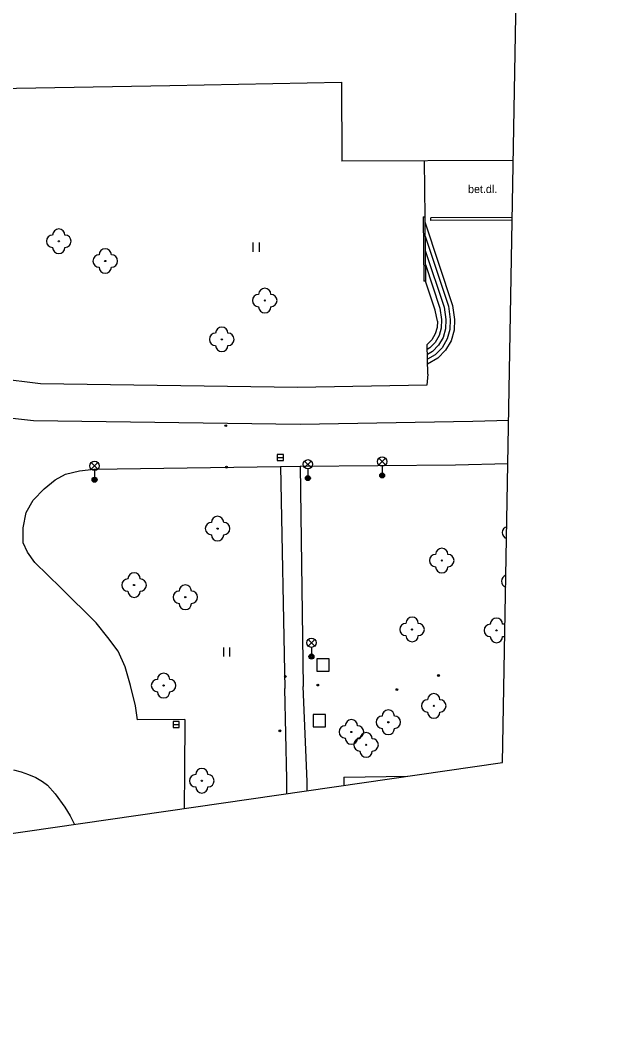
# Model space of a CAD drawing. Extents: x -641829 to -641525, y -1114855 to -1114359.
# Drawn here: x -641572.8 to -641525.3, y -1114854.7 to -1114772 of the extents above; entities that cross this region are included whole.
import ezdxf

# ---------------------------------------------------------------- set-up
doc = ezdxf.new("R2010")
doc.units = 0
for name, color, linetype in [('Vrstva 1', 7, 'Continuous'), ('Vrstva 10', 7, 'Continuous'), ('Vrstva 11', 7, 'Continuous'), ('Vrstva 20', 7, 'Continuous'), ('Vrstva 22', 7, 'Continuous'), ('Vrstva 26', 7, 'Continuous'), ('Vrstva 27', 7, 'Continuous'), ('Vrstva 33', 7, 'Continuous'), ('Vrstva 36', 7, 'Continuous'), ('Vrstva 40', 7, 'Continuous'), ('Vrstva 5', 7, 'Continuous'), ('Vrstva 7', 7, 'Continuous')]:
    doc.layers.add(name, color=color, linetype=linetype)

msp = doc.modelspace()

# ---------------------------------------------------------------- linework, layer by layer
at = {"layer": 'Vrstva 1'}
for p, q in [((-641533.66, -1114832.21), (-641525.3, -1114362.64)), ((-641689.21, -1114854.71), (-641533.66, -1114832.21))]:
    msp.add_line(p, q, dxfattribs=at)
at = {"layer": 'Vrstva 10'}
for p, q in [((-641575.38, -1114804.04), (-641571.75, -1114804.44)), ((-641571.75, -1114804.44), (-641550.1, -1114804.74)), ((-641550.1, -1114804.74), (-641536.08, -1114804.49)), ((-641536.08, -1114804.49), (-641533.165, -1114804.408)), ((-641550.1, -1114808.16), (-641537.48, -1114808.05)), ((-641537.48, -1114808.05), (-641533.228, -1114807.945)), ((-641569.98, -1114809.27), (-641569.14, -1114808.8)), ((-641569.14, -1114808.8), (-641568, -1114808.52)), ((-641568, -1114808.52), (-641566.86, -1114808.4)), ((-641566.86, -1114808.4), (-641551.7, -1114808.17)), ((-641551.7, -1114808.17), (-641550.1, -1114808.16)), ((-641570.89, -1114810), (-641569.98, -1114809.27)), ((-641571.76, -1114810.92), (-641570.89, -1114810)), ((-641572.35, -1114811.92), (-641571.76, -1114810.92)), ((-641572.59, -1114813.15), (-641572.35, -1114811.92)), ((-641572.58, -1114814.38), (-641572.59, -1114813.15)), ((-641572.23, -1114815.14), (-641572.58, -1114814.38)), ((-641571.65, -1114815.97), (-641572.23, -1114815.14)), ((-641569.52, -1114818.04), (-641571.65, -1114815.97)), ((-641566.67, -1114820.87), (-641569.52, -1114818.04)), ((-641565.72, -1114822.05), (-641566.67, -1114820.87)), ((-641564.88, -1114823.17), (-641565.72, -1114822.05)), ((-641564.31, -1114824.45), (-641564.88, -1114823.17)), ((-641563.86, -1114825.96), (-641564.31, -1114824.45)), ((-641563.46, -1114827.61), (-641563.86, -1114825.96)), ((-641563.29, -1114828.75), (-641563.46, -1114827.61)), ((-641559.45, -1114828.72), (-641563.29, -1114828.75)), ((-641559.45, -1114828.72), (-641559.5, -1114832.91)), ((-641573.38, -1114832.81), (-641572.75, -1114832.98)), ((-641572.75, -1114832.98), (-641572.16, -1114833.19)), ((-641572.16, -1114833.19), (-641571.56, -1114833.43)), ((-641571.56, -1114833.43), (-641571.02, -1114833.76)), ((-641559.5, -1114832.91), (-641559.518, -1114835.95)), ((-641571.02, -1114833.76), (-641570.61, -1114834.06)), ((-641570.61, -1114834.06), (-641570, -1114834.74)), ((-641570, -1114834.74), (-641569.19, -1114835.84)), ((-641569.19, -1114835.84), (-641568.77, -1114836.55)), ((-641568.77, -1114836.55), (-641568.418, -1114837.238))]:
    msp.add_line(p, q, dxfattribs=at)
at = {"layer": 'Vrstva 11'}
for p, q in [((-641540.03, -1114783.36), (-641539.98, -1114787.91)), ((-641540.12, -1114787.91), (-641540.06, -1114793.12)), ((-641532.872, -1114787.957), (-641539.5, -1114787.99)), ((-641539.5, -1114788.21), (-641539.5, -1114787.99)), ((-641532.876, -1114788.177), (-641539.5, -1114788.21)), ((-641539.97, -1114788.32), (-641537.72, -1114795.09)), ((-641539.96, -1114789.47), (-641538.06, -1114795.17)), ((-641539.94, -1114790.63), (-641538.41, -1114795.25)), ((-641539.93, -1114791.78), (-641538.75, -1114795.33)), ((-641539.14, -1114795.49), (-641539.91, -1114793.12)), ((-641538.96, -1114796.37), (-641539.14, -1114795.49)), ((-641538.75, -1114795.33), (-641538.63, -1114796.25)), ((-641538.41, -1114795.25), (-641538.28, -1114796.25)), ((-641538.06, -1114795.17), (-641537.92, -1114796.25)), ((-641537.72, -1114795.09), (-641537.57, -1114796.25)), ((-641539.72, -1114800.69), (-641539.79, -1114798.27)), ((-641571.18, -1114801.45), (-641574.98, -1114800.99)), ((-641550.31, -1114801.76), (-641571.18, -1114801.45)), ((-641539.72, -1114800.69), (-641539.81, -1114801.57)), ((-641539.81, -1114801.57), (-641550.31, -1114801.76)), ((-641551.7, -1114808.17), (-641551.33, -1114826.21)), ((-641550.1, -1114808.16), (-641549.84, -1114826.04)), ((-641551.19, -1114833.57), (-641551.33, -1114826.21)), ((-641549.53, -1114833.75), (-641549.84, -1114826.04)), ((-641551.183, -1114834.745), (-641551.19, -1114833.57)), ((-641549.53, -1114834.506), (-641549.53, -1114833.75))]:
    msp.add_line(p, q, dxfattribs=at)
for points in [[(-641538.96, -1114796.37), (-641538.98, -1114796.89), (-641539.13, -1114797.41), (-641539.41, -1114797.89), (-641539.79, -1114798.27)], [(-641538.63, -1114796.25), (-641538.64, -1114796.94), (-641538.81, -1114797.55), (-641539.13, -1114798.1), (-641539.58, -1114798.55), (-641539.78, -1114798.67)], [(-641538.28, -1114796.25), (-641538.29, -1114797), (-641538.49, -1114797.69), (-641538.86, -1114798.32), (-641539.36, -1114798.83), (-641539.77, -1114799.07)], [(-641537.92, -1114796.25), (-641537.94, -1114797.05), (-641538.17, -1114797.82), (-641538.58, -1114798.53), (-641539.15, -1114799.1), (-641539.76, -1114799.47)], [(-641537.57, -1114796.25), (-641537.6, -1114797.1), (-641537.84, -1114797.96), (-641538.3, -1114798.74), (-641538.93, -1114799.38), (-641539.75, -1114799.87)]]:
    msp.add_lwpolyline(points, dxfattribs=at)
at = {"layer": 'Vrstva 20'}
for centre, radius in [((-641556.14, -1114804.86), 0.075), ((-641556.14, -1114804.86), 0.0204), ((-641556.08, -1114808.23), 0.075), ((-641556.08, -1114808.23), 0.0204), ((-641551.3, -1114825.23), 0.075), ((-641551.3, -1114825.23), 0.0204), ((-641538.86, -1114825.15), 0.075), ((-641538.86, -1114825.15), 0.0204), ((-641548.67, -1114825.92), 0.075), ((-641548.67, -1114825.92), 0.0204), ((-641542.24, -1114826.29), 0.075), ((-641542.24, -1114826.29), 0.0204), ((-641551.74, -1114829.64), 0.075), ((-641551.74, -1114829.64), 0.0204)]:
    msp.add_circle(centre, radius, dxfattribs=at)
at = {"layer": 'Vrstva 22'}
for centre in [(-641569.69, -1114789.89), (-641565.92, -1114791.49), (-641552.97, -1114794.7), (-641556.46, -1114797.85), (-641556.8, -1114813.22), (-641538.6, -1114815.81), (-641563.58, -1114817.8), (-641559.42, -1114818.79), (-641541.01, -1114821.41), (-641534.16, -1114821.48), (-641561.18, -1114825.96), (-641539.25, -1114827.61), (-641542.94, -1114828.94), (-641545.94, -1114829.73), (-641544.74, -1114830.78), (-641558.08, -1114833.69)]:
    msp.add_circle(centre, 0.05, dxfattribs=at)
for centre, start, end in [((-641569.69, -1114789.39), 0, 180), ((-641570.19, -1114789.89), 90, 270), ((-641569.19, -1114789.89), 270, 90), ((-641569.69, -1114790.39), 180, 0), ((-641565.92, -1114790.99), 0, 180), ((-641566.42, -1114791.49), 90, 270), ((-641565.42, -1114791.49), 270, 90), ((-641565.92, -1114791.99), 180, 0), ((-641552.97, -1114794.2), 0, 180), ((-641553.47, -1114794.7), 90, 270), ((-641552.47, -1114794.7), 270, 90), ((-641552.97, -1114795.2), 180, 0), ((-641556.46, -1114797.35), 0, 180), ((-641556.96, -1114797.85), 90, 270), ((-641555.96, -1114797.85), 270, 90), ((-641556.46, -1114798.35), 180, 0), ((-641557.3, -1114813.22), 90, 270), ((-641556.8, -1114812.72), 0, 180), ((-641556.3, -1114813.22), 270, 90), ((-641556.8, -1114813.72), 180, 0), ((-641533.19, -1114813.55), 104.97358, 252.98651), ((-641539.1, -1114815.81), 90, 270), ((-641538.6, -1114815.31), 0, 180), ((-641538.1, -1114815.81), 270, 90), ((-641538.6, -1114816.31), 180, 0), ((-641563.58, -1114817.3), 0, 180), ((-641533.26, -1114817.49), 104.99096, 252.96912), ((-641564.08, -1114817.8), 90, 270), ((-641563.08, -1114817.8), 270, 90), ((-641559.42, -1114818.29), 0, 180), ((-641563.58, -1114818.3), 180, 0), ((-641559.92, -1114818.79), 90, 270), ((-641558.92, -1114818.79), 270, 90), ((-641559.42, -1114819.29), 180, 0), ((-641541.01, -1114820.91), 0, 180), ((-641534.16, -1114820.98), 0, 180), ((-641541.51, -1114821.41), 90, 270), ((-641540.51, -1114821.41), 270, 90), ((-641534.66, -1114821.48), 90, 270), ((-641533.66, -1114821.48), 66.52223, 90), ((-641541.01, -1114821.91), 180, 0), ((-641534.16, -1114821.98), 180, 0), ((-641533.66, -1114821.48), 270, 291.43785), ((-641561.18, -1114825.46), 0, 180), ((-641561.68, -1114825.96), 90, 270), ((-641560.68, -1114825.96), 270, 90), ((-641561.18, -1114826.46), 180, 0), ((-641539.75, -1114827.61), 90, 270), ((-641539.25, -1114827.11), 0, 180), ((-641538.75, -1114827.61), 270, 90), ((-641545.94, -1114829.23), 0, 180), ((-641543.44, -1114828.94), 90, 270), ((-641542.94, -1114828.44), 0, 180), ((-641542.44, -1114828.94), 270, 90), ((-641539.25, -1114828.11), 180, 0), ((-641546.44, -1114829.73), 90, 270), ((-641545.44, -1114829.73), 270, 90), ((-641542.94, -1114829.44), 180, 0), ((-641545.94, -1114830.23), 180, 0), ((-641545.24, -1114830.78), 90, 270), ((-641544.74, -1114830.28), 0, 180), ((-641544.24, -1114830.78), 270, 90), ((-641544.74, -1114831.28), 180, 0), ((-641558.08, -1114833.19), 0, 180), ((-641558.58, -1114833.69), 90, 270), ((-641557.58, -1114833.69), 270, 90), ((-641558.08, -1114834.19), 180, 0)]:
    msp.add_arc(centre, 0.5, start, end, dxfattribs=at)
at = {"layer": 'Vrstva 26'}
for points in [[(-641548.75, -1114824.78), (-641547.75, -1114824.78), (-641547.75, -1114823.78), (-641548.75, -1114823.78)], [(-641549.05, -1114829.31), (-641548.05, -1114829.31), (-641548.05, -1114828.31), (-641549.05, -1114828.31)]]:
    msp.add_lwpolyline(points, close=True, dxfattribs=at)
at = {"layer": 'Vrstva 27'}
for p, q in [((-641551.96, -1114807.44), (-641551.46, -1114807.44)), ((-641560.41, -1114829.13), (-641559.91, -1114829.13))]:
    msp.add_line(p, q, dxfattribs=at)
for points in [[(-641551.96, -1114807.69), (-641551.46, -1114807.69), (-641551.46, -1114807.19), (-641551.96, -1114807.19)], [(-641560.41, -1114829.38), (-641559.91, -1114829.38), (-641559.91, -1114828.88), (-641560.41, -1114828.88)]]:
    msp.add_lwpolyline(points, close=True, dxfattribs=at)
at = {"layer": 'Vrstva 33'}
for p, q in [((-641567.054, -1114808.39), (-641566.526, -1114807.86)), ((-641567.054, -1114807.86), (-641566.526, -1114808.39)), ((-641549.734, -1114808.26), (-641549.206, -1114807.73)), ((-641549.734, -1114807.73), (-641549.206, -1114808.26)), ((-641543.704, -1114808.04), (-641543.176, -1114807.51)), ((-641543.704, -1114807.51), (-641543.176, -1114808.04)), ((-641566.79, -1114808.5), (-641566.79, -1114809.25)), ((-641549.47, -1114808.37), (-641549.47, -1114809.12)), ((-641543.44, -1114808.15), (-641543.44, -1114808.9)), ((-641549.444, -1114822.75), (-641548.916, -1114822.22)), ((-641549.444, -1114822.22), (-641548.916, -1114822.75)), ((-641549.18, -1114822.86), (-641549.18, -1114823.61))]:
    msp.add_line(p, q, dxfattribs=at)
for centre, radius in [((-641566.79, -1114808.125), 0.375), ((-641549.47, -1114807.995), 0.375), ((-641543.44, -1114807.775), 0.375), ((-641543.44, -1114808.9), 0.2), ((-641543.44, -1114808.9), 0.145), ((-641543.44, -1114808.9), 0.0876), ((-641566.79, -1114809.25), 0.2), ((-641566.79, -1114809.25), 0.145), ((-641566.79, -1114809.25), 0.0876), ((-641549.47, -1114809.12), 0.2), ((-641549.47, -1114809.12), 0.145), ((-641549.47, -1114809.12), 0.0876), ((-641549.18, -1114822.485), 0.375), ((-641549.18, -1114823.61), 0.2), ((-641549.18, -1114823.61), 0.145), ((-641549.18, -1114823.61), 0.0876)]:
    msp.add_circle(centre, radius, dxfattribs=at)
at = {"layer": 'Vrstva 36'}
for p, q in [((-641553.904, -1114790.734), (-641553.904, -1114789.982)), ((-641553.404, -1114790.734), (-641553.404, -1114789.982)), ((-641556.304, -1114823.612), (-641556.304, -1114822.864)), ((-641555.804, -1114823.612), (-641555.804, -1114822.864))]:
    msp.add_line(p, q, dxfattribs=at)
at = {"layer": 'Vrstva 5'}
for p, q in [((-641576.17, -1114777.51), (-641560.69, -1114777.23)), ((-641560.69, -1114777.23), (-641546.73, -1114776.97)), ((-641546.73, -1114776.97), (-641546.72, -1114783.37)), ((-641532.79, -1114783.34), (-641546.72, -1114783.37)), ((-641546.56, -1114833.41), (-641541.37, -1114833.325))]:
    msp.add_line(p, q, dxfattribs=at)
msp.add_lwpolyline([(-641546.56, -1114833.41), (-641546.549, -1114834.074)], dxfattribs=at)
at = {"layer": 'Vrstva 7'}
for p, q in [((-641540.12, -1114787.91), (-641539.98, -1114787.91)), ((-641539.98, -1114787.91), (-641539.97, -1114788.32)), ((-641539.97, -1114788.32), (-641539.91, -1114793.12)), ((-641539.91, -1114793.12), (-641540.06, -1114793.12))]:
    msp.add_line(p, q, dxfattribs=at)

# ---------------------------------------------------------------- texts
at = {"layer": 'Vrstva 40'}
msp.add_text('bet.dl.', height=0.65, rotation=0.2847, dxfattribs=at).set_placement((-641536.465, -1114785.977))

doc.saveas('drawing.dxf')
